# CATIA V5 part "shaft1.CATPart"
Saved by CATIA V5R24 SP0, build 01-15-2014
Part number: shaft1
Bounding box of the stored display mesh (mm): x -10 to 10, y -10 to 12, z 0 to 100
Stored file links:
  G:\내 드라이브\04_WORK\00_LECTURE\CAD2020\exam\shaft1.CATPart
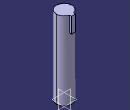
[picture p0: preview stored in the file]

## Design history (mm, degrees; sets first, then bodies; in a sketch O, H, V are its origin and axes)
Body1 (main body)
  Sketch1 on xy-plane, origin (0, 0, 0), H (1, 0, 0), V (0, 1, 0)
    circle A1 centre (0, 0) radius 10
    radius A1 = 10
  Pad1: profile Sketch1, direction (0, 0, 1), length 100
  Sketch2 on end face of Pad1, origin (0, 0, 100), H (1, 0, 0), V (0, 1, 0)
    point P1 (0, 6)
    line L1 (2.5, 12) -> (2.5, 0)
    line L2 (2.5, 0) -> (-2.5, 0)
    line L3 (-2.5, 0) -> (-2.5, 12)
    line L4 (-2.5, 12) -> (2.5, 12)
    distance L1 L3 = 5
    distance L4 H = 12
    coincidence: P1 V, H L2
    vertical: L1 V, L3 V
    horizontal: L2 H, L4 H
    equidistance: L1 L3 P1, L2 L4 P1
  Pad2: profile Sketch2, direction (0, 0, -1), length 20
